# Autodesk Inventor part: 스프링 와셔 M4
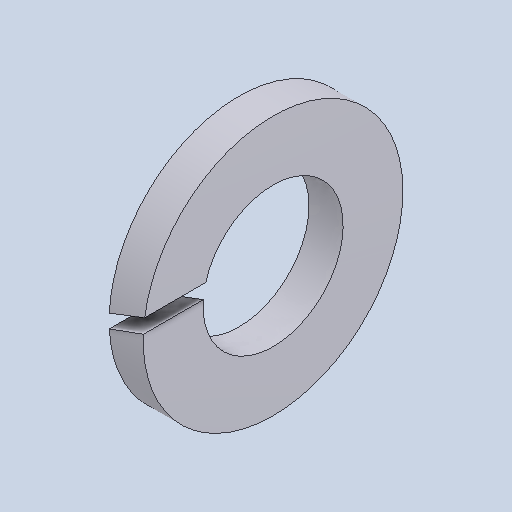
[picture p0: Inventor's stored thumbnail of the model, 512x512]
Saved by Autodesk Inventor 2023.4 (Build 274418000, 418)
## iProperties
Created: 2024-04
Part Number: 스프링 와셔 M4
Material: 강철, 연강
Description: 스프링 와셔
Document SubType Name: Modeling
Designer: EDU
Density: 7.85 g/cm^3
Appearance: 기본값
Author: jhkim
Sending System: Autodesk Inventor 2025
Preprocessor: ST-DEVELOPER v20
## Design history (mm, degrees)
node "스프링 와셔 M41"
node "솔리드1"
body "Solid1"
